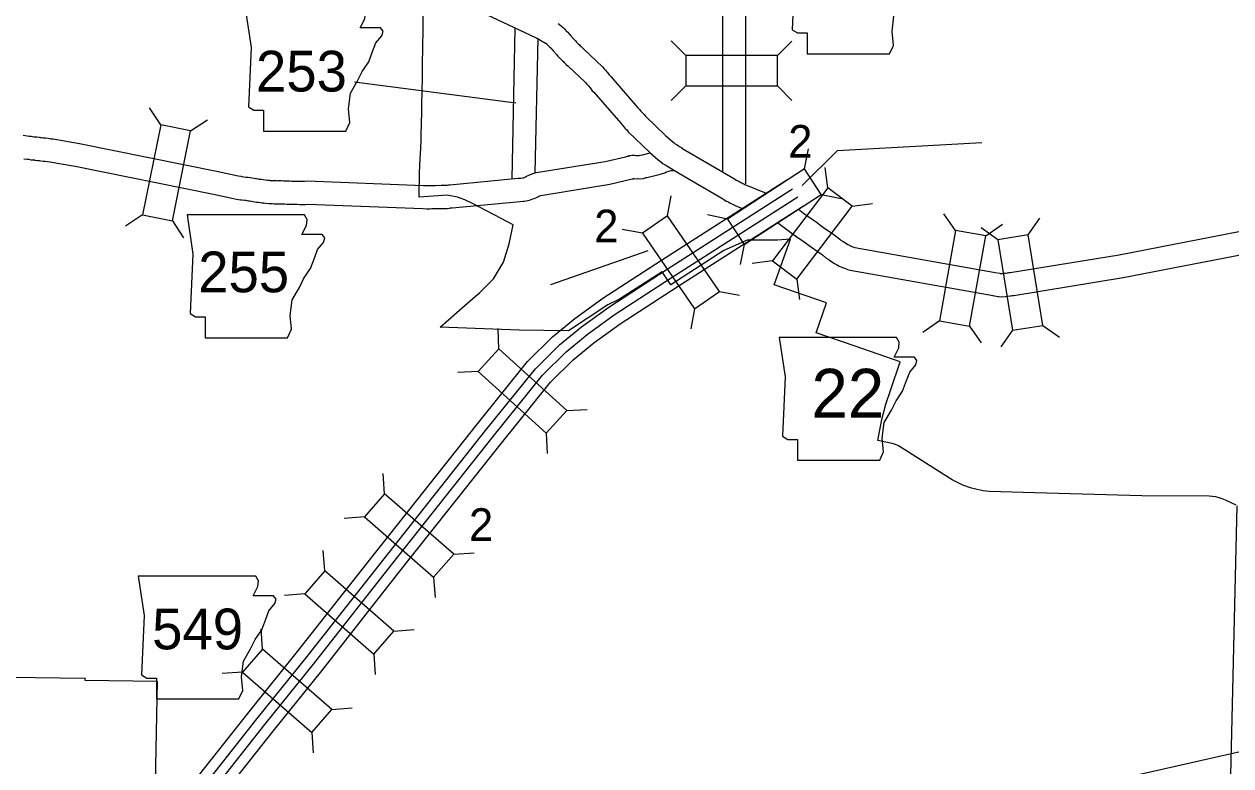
# Model space of a CAD drawing. Extents: x 1370567 to 1373900, y 377514 to 379648.
# Drawn here: x 1370881.3 to 1371037.6, y 379304.1 to 379400.2 of the extents above; entities that cross this region are included whole.
import ezdxf

# ---------------------------------------------------------------- set-up
doc = ezdxf.new("R2010")
doc.units = 0
doc.layers.add('Default', color=7, linetype='Continuous')
doc.layers.add('Survey Names', color=7, linetype='Continuous')

msp = doc.modelspace()

# ---------------------------------------------------------------- linework, layer by layer
at = {"layer": 'Default'}
for p, q in [((1370967.02, 379396.14), (1370965.16, 379398.01)), ((1370978.9, 379396.14), (1370980.77, 379398)), ((1370924.14, 379392.73), (1370945.01, 379389.98)), ((1370967.02, 379392.18), (1370965.16, 379390.31)), ((1370978.9, 379392.18), (1370980.77, 379390.31)), ((1370899.02, 379387.14), (1370897.56, 379389.34)), ((1370902.9, 379386.35), (1370905.1, 379387.8)), ((1370961.6, 379388.52), (1370961.65, 379388.47)), ((1370959.5, 379386.38), (1370959.45, 379386.43)), ((1370982.39, 379381.45), (1370982.93, 379384.03)), ((1370985.44, 379379), (1370985.09, 379381.61)), ((1370964.67, 379375.35), (1370965.15, 379377.95)), ((1370984.55, 379378.13), (1370987.14, 379377.59)), ((1370988.59, 379376.6), (1370991.21, 379376.96)), ((1370896.65, 379375.49), (1370894.45, 379374.04)), ((1370900.53, 379374.7), (1370901.99, 379372.5)), ((1370972.44, 379374.95), (1370969.86, 379375.49)), ((1371001.98, 379373.46), (1371000.47, 379375.63)), ((1371011.36, 379372.9), (1371012.9, 379375.05)), ((1370961.41, 379373.11), (1370958.81, 379373.59)), ((1371007.45, 379372.27), (1371005.31, 379373.81)), ((1371005.88, 379372.77), (1371008.05, 379374.28)), ((1370974.61, 379371.64), (1370974.06, 379369.05)), ((1370949.57, 379366.49), (1370962.14, 379370.87)), ((1370978.25, 379369.54), (1370975.64, 379369.18)), ((1370981.41, 379367.14), (1370981.76, 379364.53)), ((1370971.41, 379365.57), (1370974, 379365.09)), ((1370968.15, 379363.32), (1370967.67, 379360.73)), ((1370942.83, 379358.14), (1370942.71, 379360.77)), ((1370999.9, 379361.77), (1370997.73, 379360.26)), ((1371003.8, 379361.07), (1371005.31, 379358.91)), ((1371013.27, 379361.18), (1371015.42, 379359.64)), ((1371009.36, 379360.54), (1371007.82, 379358.4)), ((1370940.16, 379355.21), (1370937.52, 379355.09)), ((1370951.61, 379350.14), (1370954.25, 379350.26)), ((1370948.94, 379347.21), (1370949.07, 379344.57)), ((1370928.01, 379339.35), (1370927.83, 379341.98)), ((1370925.41, 379336.36), (1370922.78, 379336.18)), ((1370920.27, 379329.38), (1370920.08, 379332.02)), ((1370936.97, 379331.55), (1370939.61, 379331.73)), ((1370934.37, 379328.56), (1370934.56, 379325.93)), ((1370917.67, 379326.39), (1370915.04, 379326.21)), ((1370912.21, 379319.24), (1370912.03, 379321.88)), ((1370929.23, 379321.59), (1370931.87, 379321.78)), ((1370926.64, 379318.6), (1370926.82, 379315.97)), ((1370909.62, 379316.25), (1370906.98, 379316.07)), ((1370921.18, 379311.45), (1370923.81, 379311.64)), ((1370918.58, 379308.46), (1370918.77, 379305.83))]:
    msp.add_line(p, q, dxfattribs=at)
for points in [[(1370980.39, 379412.24), (1370981.15, 379407.17), (1370980.81, 379399.47), (1370981.49, 379399.05), (1370982.75, 379399.05), (1370982.75, 379396.34), (1370993.41, 379396.34), (1370993.92, 379397.44), (1370993.75, 379399.22), (1370994, 379401.25), (1370994.93, 379402.85), (1370995.53, 379404.04), (1370996.37, 379405.31), (1370996.88, 379406.66), (1370997.3, 379407.76), (1370998.06, 379408.69), (1370998.23, 379409.28), (1370997.9, 379409.7), (1370995.27, 379409.7), (1370995.87, 379410.89), (1370995.95, 379411.65), (1370995.6, 379412.23)], [(1370909.98, 379402.24), (1370910.74, 379397.16), (1370910.4, 379389.47), (1370911.08, 379389.04), (1370912.35, 379389.04), (1370912.35, 379386.34), (1370923.01, 379386.34), (1370923.51, 379387.44), (1370923.34, 379389.21), (1370923.6, 379391.24), (1370924.53, 379392.85), (1370925.12, 379394.04), (1370925.97, 379395.3), (1370926.47, 379396.66), (1370926.9, 379397.76), (1370927.66, 379398.69), (1370927.83, 379399.28), (1370927.49, 379399.7), (1370924.87, 379399.7), (1370925.46, 379400.89), (1370925.54, 379401.65), (1370925.19, 379402.23)], [(1370978.9, 379396.14), (1370967.02, 379396.14), (1370967.02, 379392.18), (1370978.9, 379392.18)], [(1370899.02, 379387.14), (1370896.65, 379375.49), (1370900.53, 379374.7), (1370902.9, 379386.35)], [(1370982.39, 379381.45), (1370972.44, 379374.95), (1370974.61, 379371.64), (1370984.55, 379378.13)], [(1370985.44, 379379), (1370978.25, 379369.54), (1370981.41, 379367.14), (1370988.59, 379376.6)], [(1370902.43, 379375.49), (1370903.19, 379370.41), (1370902.85, 379362.71), (1370903.53, 379362.29), (1370904.8, 379362.29), (1370904.8, 379359.58), (1370915.45, 379359.58), (1370915.96, 379360.68), (1370915.79, 379362.46), (1370916.05, 379364.49), (1370916.98, 379366.1), (1370917.57, 379367.28), (1370918.41, 379368.55), (1370918.92, 379369.9), (1370919.35, 379371), (1370920.11, 379371.93), (1370920.28, 379372.52), (1370919.94, 379372.95), (1370917.31, 379372.95), (1370917.91, 379374.13), (1370917.99, 379374.89), (1370917.64, 379375.48)], [(1370971.41, 379365.57), (1370964.67, 379375.35), (1370961.41, 379373.11), (1370968.15, 379363.32)], [(1371001.98, 379373.46), (1370999.9, 379361.77), (1371003.8, 379361.07), (1371005.88, 379372.77)], [(1371013.27, 379361.18), (1371011.36, 379372.9), (1371007.45, 379372.27), (1371009.36, 379360.54)], [(1370979.13, 379359.6), (1370979.89, 379354.52), (1370979.55, 379346.83), (1370980.23, 379346.4), (1370981.5, 379346.4), (1370981.5, 379343.7), (1370992.16, 379343.7), (1370992.66, 379344.8), (1370992.49, 379346.57), (1370992.75, 379348.6), (1370993.68, 379350.21), (1370994.27, 379351.39), (1370995.12, 379352.66), (1370995.62, 379354.02), (1370996.05, 379355.12), (1370996.81, 379356.05), (1370996.98, 379356.64), (1370996.64, 379357.06), (1370994.02, 379357.06), (1370994.61, 379358.25), (1370994.69, 379359.01), (1370994.34, 379359.59)], [(1370951.61, 379350.14), (1370942.83, 379358.14), (1370940.16, 379355.21), (1370948.94, 379347.21)], [(1370936.97, 379331.55), (1370928.01, 379339.35), (1370925.41, 379336.36), (1370934.37, 379328.56)], [(1370929.23, 379321.59), (1370920.27, 379329.38), (1370917.67, 379326.39), (1370926.64, 379318.6)], [(1370896.12, 379328.69), (1370896.89, 379323.61), (1370896.55, 379315.92), (1370897.22, 379315.49), (1370898.49, 379315.49), (1370898.49, 379312.79), (1370909.15, 379312.79), (1370909.66, 379313.89), (1370909.49, 379315.66), (1370909.74, 379317.69), (1370910.67, 379319.3), (1370911.27, 379320.48), (1370912.11, 379321.75), (1370912.62, 379323.11), (1370913.04, 379324.21), (1370913.8, 379325.14), (1370913.97, 379325.73), (1370913.63, 379326.15), (1370911.01, 379326.15), (1370911.6, 379327.34), (1370911.69, 379328.1), (1370911.34, 379328.68)], [(1370921.18, 379311.45), (1370912.21, 379319.24), (1370909.62, 379316.25), (1370918.58, 379308.46)]]:
    msp.add_lwpolyline(points, close=True, dxfattribs=at)
for points in [[(1370932.83, 379388.64), (1370932.85, 379389.8), (1370932.88, 379391.51), (1370932.91, 379393.25), (1370932.94, 379395.52), (1370932.96, 379396.63), (1370933.01, 379400.03), (1370933.15, 379409.99)], [(1370971.78, 379408.86), (1370971.77, 379381.11)], [(1370974.78, 379408.93), (1370974.77, 379379.5)], [(1370941.24, 379401.42), (1370947.58, 379398.47), (1370947.75, 379398.37), (1370947.94, 379398.26), (1370948.12, 379398.15), (1370948.35, 379398.02), (1370948.49, 379397.95), (1370948.56, 379397.91), (1370948.66, 379397.85), (1370948.87, 379397.74), (1370948.97, 379397.66), (1370949, 379397.64), (1370949.09, 379397.55), (1370949.13, 379397.51), (1370949.18, 379397.45), (1370949.36, 379397.25), (1370949.58, 379397.06), (1370949.61, 379397.04), (1370949.69, 379396.94), (1370949.89, 379396.7), (1370950.3, 379396.25), (1370950.48, 379396.05), (1370950.72, 379395.78), (1370950.85, 379395.65), (1370951.06, 379395.43), (1370951.18, 379395.33), (1370951.27, 379395.24), (1370951.38, 379395.14), (1370951.55, 379394.96), (1370951.79, 379394.74), (1370954.05, 379392.61), (1370954.18, 379392.45), (1370954.38, 379392.22), (1370954.59, 379391.99), (1370954.62, 379391.97), (1370954.65, 379391.92), (1370954.72, 379391.82), (1370954.92, 379391.57), (1370955.13, 379391.36), (1370958.6, 379387.37), (1370958.76, 379387.19), (1370958.86, 379387.06), (1370959.14, 379386.71), (1370959.28, 379386.59), (1370959.38, 379386.5), (1370959.5, 379386.38)], [(1370950.49, 379400.27), (1370950.88, 379399.98), (1370951.04, 379399.84), (1370951.19, 379399.69), (1370951.37, 379399.52), (1370951.45, 379399.41), (1370951.56, 379399.34), (1370951.77, 379399.13), (1370951.89, 379398.99), (1370951.97, 379398.89), (1370952.16, 379398.66), (1370952.54, 379398.26), (1370952.73, 379398.04), (1370952.89, 379397.85), (1370952.98, 379397.76), (1370953.11, 379397.63), (1370953.25, 379397.51), (1370953.37, 379397.39), (1370953.46, 379397.31), (1370953.65, 379397.1), (1370953.84, 379396.93), (1370956.24, 379394.67), (1370956.47, 379394.39), (1370956.62, 379394.22), (1370956.75, 379394.07), (1370956.85, 379393.98), (1370957.03, 379393.75), (1370957.12, 379393.63), (1370957.17, 379393.56), (1370957.32, 379393.42), (1370960.83, 379389.37), (1370961.05, 379389.13), (1370961.22, 379388.92), (1370961.3, 379388.82), (1370961.48, 379388.64), (1370961.6, 379388.52)], [(1370944.9, 379399.67), (1370944.48, 379380.14)], [(1370947.87, 379398.35), (1370947.5, 379380.92)], [(1371038.34, 379337.88), (1371036.94, 379338.56), (1371036.51, 379338.73), (1371036.1, 379338.85), (1371035.68, 379338.95), (1371035.26, 379339.02), (1371034.81, 379339.06), (1371026.1, 379339.12), (1371012.19, 379339.47), (1371006.34, 379339.67), (1371005.95, 379339.71), (1371005.56, 379339.76), (1371005.18, 379339.83), (1371004.79, 379339.91), (1371004.41, 379340), (1371004.03, 379340.1), (1371003.66, 379340.22), (1371003.29, 379340.35), (1371002.93, 379340.49), (1371002.57, 379340.65), (1371002.21, 379340.82), (1371001.87, 379341), (1371001.53, 379341.19), (1371001.19, 379341.39), (1370994.59, 379345.57), (1370994.2, 379345.75), (1370993.77, 379345.89), (1370991.92, 379346.25), (1370992.43, 379348.99), (1370992.93, 379350.97), (1370993.58, 379352.85), (1370994.82, 379356.47), (1370988.99, 379358.48), (1370983.94, 379360.2), (1370985.28, 379364.09), (1370978.47, 379366.41), (1370980.6, 379372.35), (1370978.91, 379372.23), (1370975, 379372.23), (1370971.97, 379370.86), (1370965.09, 379366.41), (1370963.97, 379368.13), (1370958.46, 379364.56), (1370956.94, 379363.84), (1370951.86, 379360.46), (1370945.44, 379360.56), (1370935.22, 379360.95), (1370938.47, 379363.8), (1370940.35, 379365.45), (1370942.12, 379367.22), (1370943.41, 379369.36), (1370944.14, 379371.75), (1370944.69, 379374.19), (1370943.11, 379375.02), (1370939.42, 379376.96), (1370938.43, 379377.45), (1370937.46, 379377.77), (1370936.13, 379378.04), (1370932.48, 379377.78), (1370932.56, 379381.01), (1370932.57, 379381.73), (1370932.58, 379381.98), (1370932.62, 379382.7), (1370932.66, 379383.49), (1370932.7, 379384.05), (1370932.75, 379385.21), (1370932.76, 379385.56), (1370932.81, 379387.49), (1370932.83, 379388.64)], [(1370961.65, 379388.47), (1370961.82, 379388.29), (1370961.87, 379388.22), (1370964.41, 379385.78), (1370965.36, 379384.93), (1370965.53, 379384.81), (1370965.67, 379384.69), (1370965.9, 379384.54), (1370966.11, 379384.41), (1370966.22, 379384.34), (1370966.5, 379384.17), (1370966.54, 379384.13), (1370973.36, 379380.14), (1370973.57, 379379.99), (1370973.6, 379379.97), (1370973.68, 379379.93), (1370973.93, 379379.82), (1370974.17, 379379.68), (1370974.18, 379379.67), (1370974.28, 379379.63), (1370974.41, 379379.56), (1370974.54, 379379.5), (1370974.67, 379379.44), (1370977.44, 379378.3)], [(1370881.2, 379385.79), (1370881.46, 379385.75), (1370881.72, 379385.71), (1370881.97, 379385.68), (1370882.23, 379385.67), (1370882.6, 379385.6), (1370882.64, 379385.6), (1370882.99, 379385.6), (1370883.28, 379385.54), (1370883.42, 379385.52), (1370883.58, 379385.5), (1370883.8, 379385.48), (1370884.1, 379385.45), (1370884.44, 379385.41), (1370884.78, 379385.35), (1370885.08, 379385.32), (1370888.51, 379384.74), (1370906.48, 379381.09), (1370909.06, 379380.55), (1370909.41, 379380.48), (1370909.54, 379380.45), (1370909.75, 379380.43), (1370910.03, 379380.39), (1370910.13, 379380.37), (1370910.37, 379380.36), (1370910.64, 379380.31), (1370910.84, 379380.29), (1370911.13, 379380.24), (1370911.28, 379380.21), (1370911.41, 379380.19), (1370911.64, 379380.15), (1370911.79, 379380.13), (1370912.02, 379380.1), (1370912.28, 379380.07), (1370912.55, 379380.04), (1370912.86, 379380), (1370913.07, 379379.96), (1370913.21, 379379.95), (1370913.53, 379379.94), (1370913.76, 379379.93), (1370914.04, 379379.94), (1370914.21, 379379.91), (1370914.29, 379379.92), (1370914.65, 379379.92), (1370914.92, 379379.9), (1370915.22, 379379.9), (1370915.4, 379379.88), (1370915.69, 379379.89), (1370916.01, 379379.87), (1370916.15, 379379.87), (1370916.53, 379379.87), (1370916.87, 379379.85), (1370917.09, 379379.84), (1370917.64, 379379.85), (1370917.99, 379379.88), (1370933.06, 379379.3), (1370933.54, 379379.28), (1370933.81, 379379.29), (1370934.08, 379379.3), (1370934.36, 379379.3), (1370934.63, 379379.31), (1370934.94, 379379.32), (1370935.14, 379379.31), (1370935.35, 379379.32), (1370935.57, 379379.32), (1370935.73, 379379.32), (1370935.87, 379379.32), (1370936.12, 379379.35), (1370936.28, 379379.37), (1370936.46, 379379.39), (1370945.32, 379380.22), (1370945.65, 379380.25), (1370945.92, 379380.28), (1370945.97, 379380.28), (1370946.02, 379380.3), (1370946.11, 379380.33), (1370946.23, 379380.38), (1370946.27, 379380.4), (1370946.42, 379380.48), (1370946.61, 379380.58), (1370946.8, 379380.68), (1370947.05, 379380.77), (1370947.15, 379380.8), (1370947.24, 379380.84), (1370947.41, 379380.9), (1370947.67, 379380.96), (1370956.6, 379382.4), (1370959.24, 379383.01), (1370959.26, 379383.02), (1370959.57, 379383.12), (1370959.79, 379383.15)], [(1370959.45, 379386.43), (1370959.49, 379386.39), (1370959.59, 379386.26), (1370962.37, 379383.57), (1370963.47, 379382.6), (1370963.63, 379382.48), (1370963.75, 379382.38), (1370964.1, 379382.1), (1370964.3, 379382.01), (1370964.34, 379381.98), (1370964.46, 379381.91), (1370964.57, 379381.83), (1370966.22, 379380.84), (1370971.7, 379377.64), (1370971.94, 379377.46), (1370972.27, 379377.28), (1370972.44, 379377.2), (1370972.54, 379377.16), (1370972.59, 379377.13), (1370972.77, 379377.01), (1370972.99, 379376.92), (1370973.08, 379376.87), (1370973.26, 379376.79), (1370973.44, 379376.7), (1370974.35, 379376.33)], [(1370982.09, 379379.3), (1370986.68, 379383.82), (1371005.36, 379384.87)], [(1370881.3, 379382.74), (1370881.71, 379382.69), (1370881.91, 379382.68), (1370882.18, 379382.63), (1370882.5, 379382.6), (1370882.67, 379382.6), (1370882.72, 379382.59), (1370883.06, 379382.54), (1370883.31, 379382.51), (1370883.48, 379382.5), (1370883.78, 379382.46), (1370884.04, 379382.44), (1370884.34, 379382.39), (1370884.66, 379382.35), (1370887.96, 379381.79), (1370905.88, 379378.15), (1370908.45, 379377.61), (1370908.82, 379377.54), (1370909.09, 379377.48), (1370909.36, 379377.45), (1370909.58, 379377.42), (1370909.86, 379377.38), (1370910.04, 379377.37), (1370910.17, 379377.35), (1370910.41, 379377.32), (1370910.58, 379377.29), (1370910.79, 379377.24), (1370910.98, 379377.22), (1370911.17, 379377.19), (1370911.42, 379377.15), (1370911.69, 379377.12), (1370911.91, 379377.1), (1370912.18, 379377.06), (1370912.37, 379377.04), (1370912.61, 379376.99), (1370913.04, 379376.95), (1370913.46, 379376.94), (1370913.73, 379376.93), (1370913.85, 379376.93), (1370914.1, 379376.9), (1370914.4, 379376.92), (1370914.56, 379376.92), (1370914.77, 379376.91), (1370915.07, 379376.9), (1370915.35, 379376.88), (1370915.65, 379376.89), (1370915.84, 379376.88), (1370916.1, 379376.87), (1370916.46, 379376.87), (1370916.69, 379376.86), (1370917.04, 379376.84), (1370917.79, 379376.85), (1370918.05, 379376.87), (1370932.96, 379376.3), (1370933.51, 379376.28), (1370933.89, 379376.29), (1370934.16, 379376.3), (1370934.39, 379376.3), (1370934.71, 379376.31), (1370934.96, 379376.32), (1370935.18, 379376.31), (1370935.37, 379376.32), (1370935.51, 379376.31), (1370935.83, 379376.32), (1370936.14, 379376.33), (1370936.42, 379376.37), (1370936.56, 379376.38), (1370936.77, 379376.4), (1370945.6, 379377.23), (1370945.96, 379377.27), (1370946.1, 379377.28), (1370946.37, 379377.29), (1370946.77, 379377.39), (1370946.99, 379377.46), (1370947.22, 379377.55), (1370947.4, 379377.62), (1370947.6, 379377.71), (1370947.85, 379377.84), (1370947.98, 379377.91), (1370948.01, 379377.93), (1370948.11, 379377.96), (1370948.25, 379378.01), (1370957.19, 379379.45), (1370959.93, 379380.09), (1370960.25, 379380.17), (1370960.32, 379380.2)], [(1370959.57, 379383.11), (1370959.77, 379383.17), (1370960.09, 379383.2), (1370960.22, 379383.2), (1370960.39, 379383.2), (1370960.55, 379383.19), (1370960.7, 379383.18), (1370960.88, 379383.19), (1370960.98, 379383.18), (1370961.13, 379383.24), (1370961.43, 379383.28), (1370962.43, 379383.52)], [(1370960.19, 379380.2), (1370960.25, 379380.2), (1370960.28, 379380.2), (1370960.34, 379380.2), (1370960.73, 379380.17), (1370960.81, 379380.18), (1370961.06, 379380.14), (1370961.55, 379380.21), (1370961.85, 379380.31), (1370961.85, 379380.31), (1370962, 379380.33), (1370963.57, 379380.71), (1370963.89, 379380.79), (1370964.32, 379380.92), (1370964.52, 379381.04), (1370965.15, 379381.25), (1370965.16, 379381.25), (1370965.19, 379381.25), (1370965.38, 379381.25), (1370965.52, 379381.28)], [(1370885.53, 379258.97), (1370885.95, 379263.29), (1370886.23, 379265.14), (1370887.18, 379268.98), (1370888, 379272.84), (1370888.84, 379276.51), (1370889.7, 379279.65), (1370891.11, 379283.32), (1370892.98, 379287.35), (1370894.49, 379290.06), (1370896.38, 379292.97), (1370902.27, 379300.75), (1370910.46, 379311.11), (1370916.74, 379318.94), (1370926.87, 379331.81), (1370940.04, 379348.43), (1370946.53, 379356.49), (1370949.77, 379359.68), (1370952.66, 379362.08), (1370956.27, 379364.68), (1370963.87, 379369.63), (1370980.13, 379380.02)], [(1370886.83, 379258.12), (1370887.32, 379263.12), (1370887.58, 379264.88), (1370888.52, 379268.67), (1370889.34, 379272.54), (1370890.17, 379276.18), (1370891.01, 379279.22), (1370892.37, 379282.78), (1370894.2, 379286.73), (1370895.67, 379289.35), (1370897.5, 379292.18), (1370903.36, 379299.91), (1370911.53, 379310.26), (1370917.82, 379318.08), (1370927.95, 379330.96), (1370941.11, 379347.57), (1370947.55, 379355.56), (1370950.69, 379358.66), (1370953.51, 379361), (1370957.05, 379363.55), (1370964.61, 379368.47), (1370980.87, 379378.87)], [(1370888, 379257.21), (1370888.56, 379262.97), (1370888.81, 379264.63), (1370889.73, 379268.39), (1370890.56, 379272.27), (1370891.38, 379275.87), (1370892.2, 379278.83), (1370893.53, 379282.3), (1370895.32, 379286.16), (1370896.74, 379288.71), (1370898.53, 379291.46), (1370904.35, 379299.14), (1370912.51, 379309.48), (1370918.8, 379317.31), (1370928.93, 379330.18), (1370942.09, 379346.79), (1370948.48, 379354.72), (1370951.53, 379357.73), (1370954.27, 379360.01), (1370957.76, 379362.52), (1370965.29, 379367.42), (1370981.55, 379377.81)], [(1370889.29, 379256.2), (1370889.92, 379262.8), (1370890.16, 379264.36), (1370891.07, 379268.08), (1370891.9, 379271.98), (1370892.72, 379275.54), (1370893.51, 379278.4), (1370894.79, 379281.76), (1370896.54, 379285.53), (1370897.92, 379288), (1370899.65, 379290.67), (1370905.44, 379298.3), (1370913.59, 379308.62), (1370919.87, 379316.45), (1370930.01, 379329.33), (1370943.16, 379345.93), (1370949.5, 379353.8), (1370952.46, 379356.71), (1370955.11, 379358.92), (1370958.53, 379361.38), (1370966.03, 379366.27), (1370982.29, 379376.65)], [(1370981.63, 379376.23), (1370982.27, 379375.72), (1370983.42, 379374.91), (1370983.92, 379374.58), (1370984.34, 379374.25), (1370985.05, 379373.74), (1370985.91, 379373.16), (1370986.58, 379372.66), (1370986.98, 379372.32), (1370987.13, 379372.22), (1370987.42, 379372.02), (1370987.63, 379371.9), (1370987.84, 379371.77), (1370988.04, 379371.65), (1370988.22, 379371.55), (1370988.38, 379371.48), (1370988.56, 379371.4), (1370988.69, 379371.35), (1370988.82, 379371.31), (1370988.93, 379371.28), (1371007.38, 379367.99)], [(1370978.93, 379374.51), (1370979.95, 379373.73), (1370980.47, 379373.32), (1370981.73, 379372.43), (1370982.18, 379372.13), (1370982.56, 379371.85), (1370983.32, 379371.29), (1370984.17, 379370.71), (1370984.72, 379370.3), (1370985.19, 379369.91), (1370985.46, 379369.73), (1370985.78, 379369.52), (1370986.08, 379369.33), (1370986.3, 379369.2), (1370986.55, 379369.04), (1370986.89, 379368.86), (1370987.11, 379368.76), (1370987.44, 379368.61), (1370987.7, 379368.52), (1370987.96, 379368.43), (1370988.32, 379368.34), (1371006.85, 379365.04)], [(1371007.45, 379367.98), (1371007.71, 379367.92), (1371007.74, 379367.91), (1371007.99, 379367.89), (1371008, 379367.89), (1371008.25, 379367.94), (1371008.36, 379367.93), (1371008.43, 379367.95), (1371008.66, 379367.98), (1371008.77, 379367.99), (1371008.93, 379368.01), (1371009.07, 379368.03), (1371023.16, 379370.33), (1371038.68, 379373.34), (1371039.38, 379373.5), (1371041.74, 379374.2)], [(1371006.77, 379365.05), (1371007.26, 379364.94), (1371007.48, 379364.93), (1371007.57, 379364.92), (1371007.88, 379364.86), (1371008.44, 379364.91), (1371009.05, 379365.01), (1371009.13, 379365.01), (1371009.31, 379365.04), (1371009.51, 379365.06), (1371023.69, 379367.38), (1371039.31, 379370.41), (1371040.14, 379370.6), (1371040.87, 379370.82)], [(1370876.23, 379315.65), (1370889.22, 379315.49), (1370889.21, 379315.22), (1370898.56, 379315.1), (1370898.31, 379301.89), (1370904.78, 379301.93), (1370904.88, 379289.59), (1370914.47, 379301.48), (1370918.02, 379301.34), (1370944.64, 379300.66), (1370971.18, 379300.49), (1370997.78, 379299.84), (1371024.18, 379299.35), (1371037.53, 379299.24), (1371038.47, 379337.82)]]:
    msp.add_lwpolyline(points, dxfattribs=at)
at = {"layer": 'Survey Names'}
msp.add_line((1371498.51, 379409.91), (1370792.1, 379250.17), dxfattribs=at)

# ---------------------------------------------------------------- texts
at = {"layer": 'Default'}
for s, height, p in [('253', 5.28, (1370911.36, 379391.46)), ('2', 4.22, (1370980.3, 379382.91)), ('2', 4.22, (1370955.17, 379371.94)), ('255', 5.28, (1370903.88, 379365.46)), ('22', 6.336, (1370983.31, 379349.21)), ('2', 4.22, (1370938.95, 379333.27)), ('549', 5.28, (1370897.91, 379319.22))]:
    msp.add_text(s, height=height, dxfattribs=at).set_placement(p)

doc.saveas('drawing.dxf')
